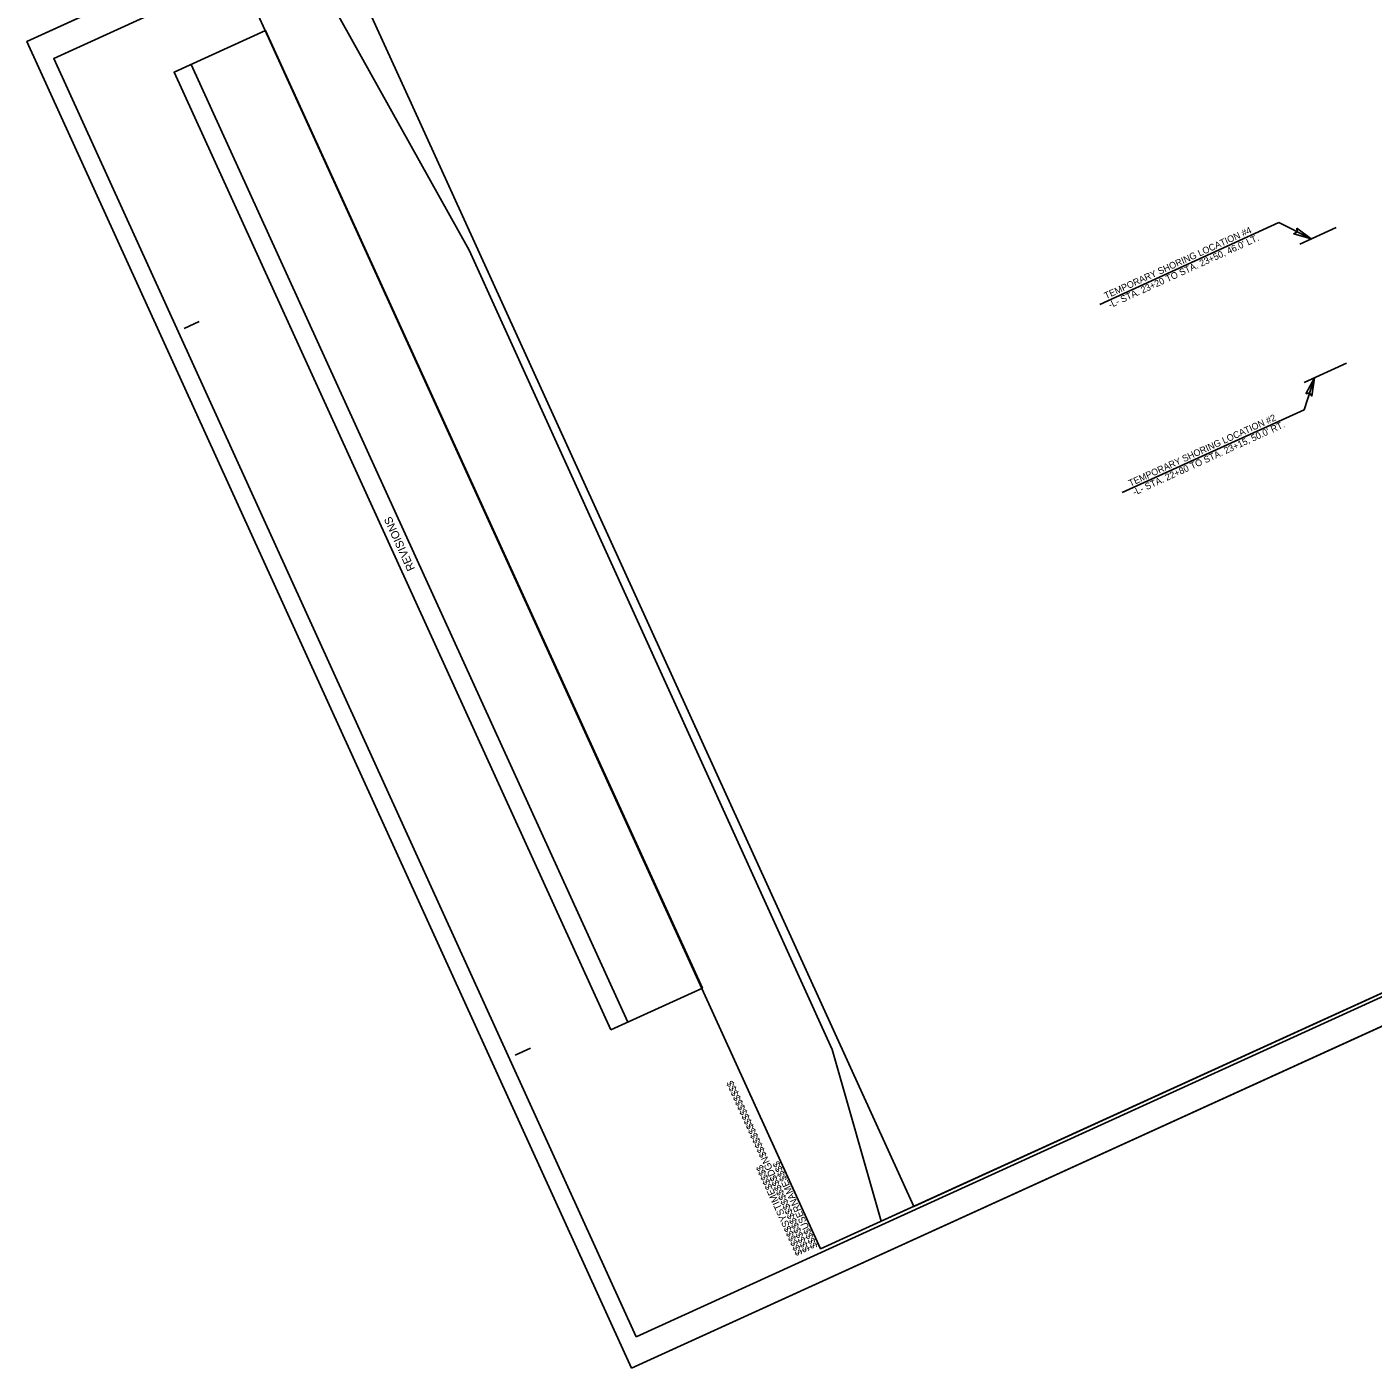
# Model space of a CAD drawing. Extents: x 2247910 to 2249896, y 662531 to 664261.
# Drawn here: x 2247910 to 2248921, y 662531 to 663539 of the extents above; entities that cross this region are included whole.
import ezdxf

# ---------------------------------------------------------------- set-up
doc = ezdxf.new("R2010")
doc.units = 0
for name, color, linetype in [('Prop Temporary Shoring', 7, 'Continuous'), ('Prop Temporary Shoring Leader Line', 7, 'Continuous'), ('Prop Terminator CELL', 7, 'Continuous'), ('Sheet Block Revision CELL', 7, 'Continuous'), ('Sheet Clip Boundary CELL', 7, 'Continuous'), ('Sheet Cutting Line CELL', 7, 'Continuous'), ('Sheet Layout Plan Border', 7, 'Continuous'), ('Sheet Plan CELL', 7, 'Continuous'), ('Sheet Plan Layout CELL', 7, 'Continuous'), ('Sheet Plot Border Inside CELL', 7, 'Continuous'), ('Sheet Plot Border Outside CELL', 7, 'Continuous')]:
    doc.layers.add(name, color=color, linetype=linetype)

msp = doc.modelspace()

# ---------------------------------------------------------------- linework, layer by layer
at = {"layer": 'Prop Temporary Shoring'}
for p, q in [((2248865.7, 663375.5), (2248893, 663388)), ((2248869, 663271.6), (2248900.8, 663286.1))]:
    msp.add_line(p, q, dxfattribs=at)
at = {"layer": 'Prop Temporary Shoring Leader Line'}
for p, q in [((2248715.4, 663330.3), (2248849.9, 663391.7)), ((2248849.9, 663391.7), (2248874.3, 663379.5)), ((2248868.9, 663251.2), (2248876.7, 663275.1)), ((2248732.3, 663189), (2248868.9, 663251.2))]:
    msp.add_line(p, q, dxfattribs=at)
at = {"layer": 'Prop Terminator CELL'}
for points in [[(2248863.3, 663387.6), (2248874.3, 663379.5), (2248861.1, 663383.4), (2248863.7, 663384.8)], [(2248870.3, 663263), (2248876.7, 663275.1), (2248874.7, 663261.4), (2248873, 663263.8)]]:
    msp.add_lwpolyline(points, close=True, dxfattribs=at)
at = {"layer": 'Sheet Block Revision CELL'}
msp.add_line((2248360.8, 662791.1), (2248032.9, 663510.5), dxfattribs=at)
msp.add_lwpolyline([(2248348.2, 662785.3), (2248020.1, 663504.7), (2248088.7, 663536), (2248416.9, 662816.6)], close=True, dxfattribs=at)
at = {"layer": 'Sheet Clip Boundary CELL'}
msp.add_lwpolyline([(2248241.7, 663371.1), (2248514.4, 662770.6), (2248551.2, 662641.6), (2249825.2, 663222.1), (2249780.7, 663312.1), (2249743.4, 663294.9), (2249677.4, 663353.6), (2249425.3, 663908.7), (2249477.5, 663985.1), (2249305.3, 663906.7), (2249217.6, 664099.1), (2248115.8, 663597.1)], close=True, dxfattribs=at)
at = {"layer": 'Sheet Cutting Line CELL'}
for p, q in [((2249441.4, 664225.8), (2247909.5, 663527.8)), ((2247909.5, 663527.8), (2248363.6, 662531.3)), ((2248363.6, 662531.3), (2249895.5, 663229.4))]:
    msp.add_line(p, q, dxfattribs=at)
at = {"layer": 'Sheet Layout Plan Border'}
msp.add_lwpolyline([(2248198.1, 663481.5), (2248575.8, 662652.8), (2249849.7, 663233.3), (2249502.1, 663996.3), (2249329.8, 663917.8), (2249242.1, 664110.3), (2248140.4, 663608.2)], close=True, dxfattribs=at)
at = {"layer": 'Sheet Plan CELL'}
for p, q in [((2248027.5, 663312.3), (2248038.8, 663317.5)), ((2248276.3, 662766.3), (2248287.7, 662771.5)), ((2248505.7, 662620.9), (2248505.7, 662620.9))]:
    msp.add_line(p, q, dxfattribs=at)
for points in [[(2249435.3, 664198.3), (2248070.3, 663576.3), (2248505.7, 662620.9), (2249870.7, 663242.8)], [(2248505.7, 662620.9), (2248070.3, 663576.3), (2249253.3, 664115.4), (2249268.8, 664081.2), (2249359.9, 664122.7), (2249406.5, 664020.3), (2249497.5, 664061.8), (2249870.7, 663242.8)]]:
    msp.add_lwpolyline(points, close=True, dxfattribs=at)
at = {"layer": 'Sheet Plan Layout CELL'}
msp.add_lwpolyline([(2248070.3, 663576.3), (2248505.7, 662620.9), (2249870.7, 663242.8), (2249523, 664005.9), (2249305.3, 663906.7), (2249217.6, 664099.1)], close=True, dxfattribs=at)
at = {"layer": 'Sheet Plot Border Inside CELL'}
msp.add_lwpolyline([(2248367.1, 662554.9), (2249883.1, 663245.8), (2249445.6, 664205.8), (2247929.6, 663514.9)], close=True, dxfattribs=at)
at = {"layer": 'Sheet Plot Border Outside CELL'}
msp.add_lwpolyline([(2248363.6, 662531.3), (2249895.5, 663229.4), (2249441.4, 664225.8), (2247909.5, 663527.8)], close=True, dxfattribs=at)

# ---------------------------------------------------------------- texts
at = {"layer": 'Prop Temporary Shoring'}
for s, p in [('TEMPORARY SHORING LOCATION #4', (2248720.1, 663334.2)), ("-L- STA. 23+20 TO STA. 23+50, 46.0' LT.", (2248723.2, 663327.3)), ('TEMPORARY SHORING LOCATION #2', (2248738.4, 663193.4)), ("-L- STA. 22+80 TO STA. 23+15, 50.0' RT.", (2248741.5, 663186.6))]:
    msp.add_text(s, height=5, rotation=24.4979, dxfattribs=at).set_placement(p)
at = {"layer": 'Sheet Block Revision CELL'}
msp.add_text('REVISIONS', height=6, rotation=114.4979, dxfattribs=at).set_placement((2248201.1, 663131.7))
at = {"layer": 'Sheet Plan CELL'}
for s, p in [('$$$$$$$$$$$$$$$$DGN$$$$$$$$$$$$$$$$', (2248497.8, 662619.8)), ('$$$$USERNAME$$$$', (2248503.7, 662622.6)), ('$$$$$$SYSTIME$$$$$', (2248492.3, 662617.3))]:
    msp.add_text(s, height=5.25, rotation=114.4979, dxfattribs=at).set_placement(p)

doc.saveas('drawing.dxf')
